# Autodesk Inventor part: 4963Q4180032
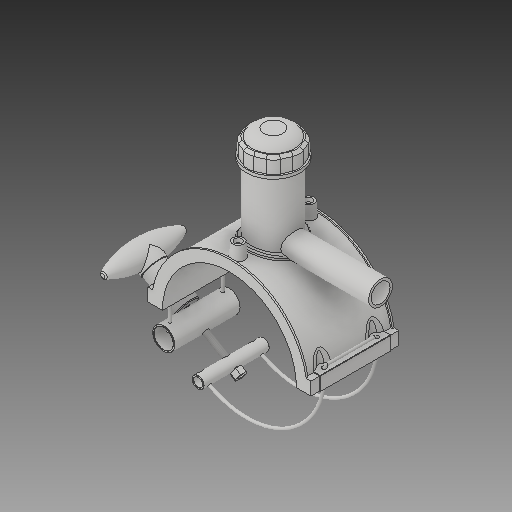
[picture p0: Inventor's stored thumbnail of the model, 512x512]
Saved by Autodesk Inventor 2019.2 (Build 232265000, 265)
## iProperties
Created: 2017-07
Part Number: 4963Q4180032
Material: Generic
Description: PLASSON TAPPING SADDLE 180x32
Document SubType Name: Modeling
Designer: KIM
Mass: 1712.7 g
Surface Area: 2671.49 cm^2
Volume: 1712.7 cm^3
Density: 1 g/cm^3
Appearance: Default
Author: KIM
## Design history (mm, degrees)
derived "4963Q4 (new clamping).ipt"
feature "Solid1::4963Q4 (new clamping).ipt"
feature "Solid2::4963Q4 (new clamping).ipt"
feature "Solid4::4963Q4 (new clamping).ipt"
feature "Solid5::4963Q4 (new clamping).ipt"
feature "Solid6::4963Q4 (new clamping).ipt"
feature "Solid7::4963Q4 (new clamping).ipt"
feature "Solid8::4963Q4 (new clamping).ipt"
feature "Solid9::4963Q4 (new clamping).ipt" dims "d70" = 15
feature "Solid10::4963Q4 (new clamping).ipt"
tag "TaggingFeature1"
body "Solid1"
body "Solid2"
body "Solid3"
body "Solid4"
body "Solid5"
body "Solid6"
body "Solid7"
other parameters: "d2" = 219, "d4" = 118, "d5" = 0, "d6" = 0.1, "d8" = 0, "d19" = 6, "d20" = 6, "d21" = 70.8, "d23" = 0, "d24" = 35.4, "d40" = 106.704, "d41" = 72, "d43" = 0, "d45" = 0, "d47" = 173.4, "d72" = 0, "d73" = 6, "d77" = 9, "d79" = 15, "d80" = 47.2, "d82" = 5 deg, "d84" = 4, "d85" = 14, "d86" = 0, "d87" = 3, "d88" = 0, "d89" = 1, "d90" = 1, "d91" = 94.4, "d92" = 0, "d93" = 0.5, "d94" = 94.73684, "d96" = 209.304, "d97" = 2.36, "d98" = 0, "d102" = 1.8, "d120" = 140 deg, "d121" = 24.228, "d122" = 20 deg, "d123" = 410.4, "d124" = 123.12, "d126" = 0, "d143" = 185.4, "d145" = 19.38462, "d149" = 2.7, "d150" = 21.32308, "d153" = 118, "d154" = 0, "d156" = 102.6, "d157" = 160 deg, "d159" = 5.04, "d161" = 2.7, "d162" = 70.8, "d163" = 0, "d167" = 18, "d168" = 100.09756, "d170" = 3.75, "d172" = 0, "d173" = 1, "d176" = 20 deg, "d177" = 12.6, "d178" = 25.2, "d180" = 0, "d183" = 10.08, "d184" = 10.08, "d185" = 38.35, "d186" = 38.35, "d187" = 102.6, "d188" = 7.56, "d189" = 12.6, "d190" = 0, "d191" = 153.9, "d193" = 7, "d194" = 4.13, "d195" = 90 deg, "d197" = 0, "d199" = 0, "d200" = 12.6, "d203" = 138, "d204" = 68.4, "d205" = 50.4, "d206" = 61.2, "d207" = 103.5, "d208" = 107.64, "d209" = 128.34, "d210" = 61.92, "d211" = 72, "d212" = 57.6, "d213" = 1.8, "d216" = 0, "d217" = 18, "d218" = 18, "d219" = 3.6, "d224" = 0, "d230" = 3.6, "d245" = 35.4, "d246" = 35.4, "d247" = 6, "d248" = 6, "d257" = 108, "d258" = 144, "d259" = 25.6, "d260" = 32, "d263" = 219, "d265" = 0, "d267" = 13.00006, "d268" = 2.60001, "d269" = 2.60001, "d271" = 2.60001, "d273" = 0, "d274" = 23.56194, "d275" = 144, "d277" = 72, "d278" = 288, "d280" = 0, "d283" = 0, "d285" = 0, "d286" = 17.5, "d287" = 17.5, "d289" = 0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
